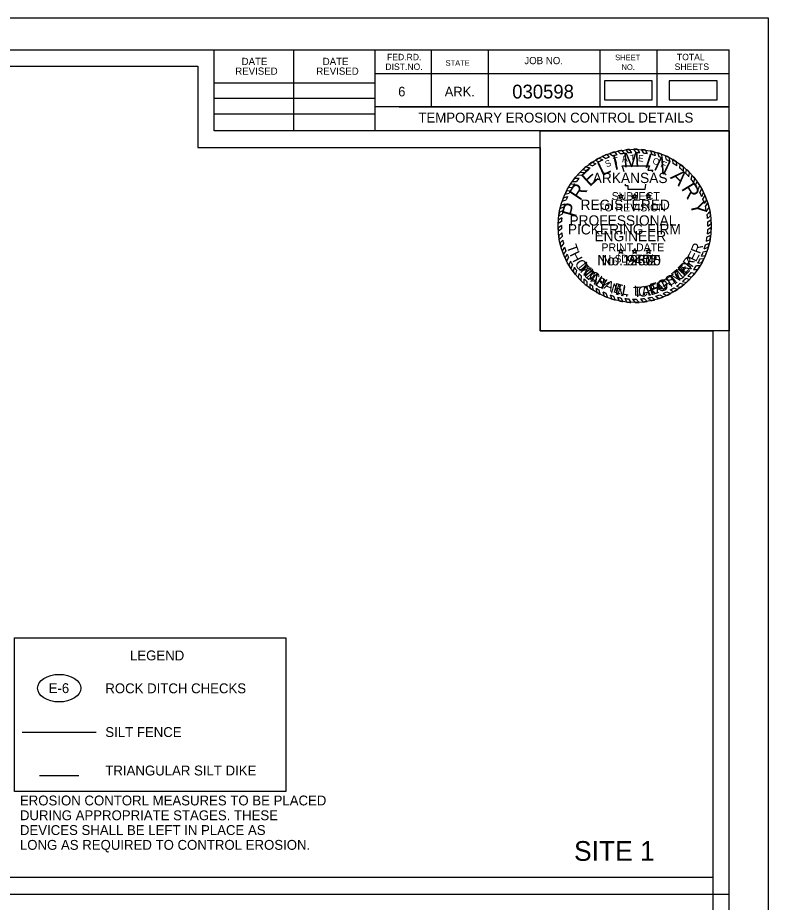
# Model space of a CAD drawing. Extents: x 814841 to 962585, y -174183 to 1802800.
# Drawn here: x 816051 to 816507, y 1802262 to 1802800 of the extents above; entities that cross this region are included whole.
import ezdxf

# ---------------------------------------------------------------- set-up
doc = ezdxf.new("R2010")
doc.units = 0
for name, color, linetype in [('_Silt Dike Legend', 7, 'Continuous'), ('Default', 7, 'Continuous'), ('Legend', 7, 'Continuous'), ('R_Border', 7, 'Continuous'), ('R_Border Notes', 7, 'Continuous'), ('R_Border Plan-Plan', 7, 'Continuous'), ('R_No Plot', 7, 'Continuous'), ('STAMP_PE_CRAFTON', 7, 'Continuous'), ('STAMP_PE_FOSTER', 7, 'Continuous'), ('STAMP_PE_SEAL-INFO', 7, 'Continuous'), ('STAMP_PE_TAEGTMEYER', 7, 'Continuous'), ('STAMP_PE_TXT', 7, 'Continuous'), ('STAMP_PRELIMINARY', 7, 'Continuous'), ('Veg Buffer', 7, 'Continuous')]:
    doc.layers.add(name, color=color, linetype=linetype)

# ---------------------------------------------------------------- blocks, each defined once
blk = doc.blocks.new('E-6')
at = {"layer": 'Default'}
blk.add_ellipse((0, 0), major_axis=(13.15, 0), ratio=0.638788, dxfattribs=at)
blk.add_text('E-6', height=6, dxfattribs=at).set_placement((-6.43, -3))

msp = doc.modelspace()

# ---------------------------------------------------------------- linework, layer by layer
at = {"layer": '_Silt Dike Legend'}
msp.add_line((816063.99, 1802339.12), (816087.99, 1802339.12), dxfattribs=at)
at = {"layer": 'Legend'}
msp.add_line((816053.56, 1802365.5), (816098.58, 1802365.5), dxfattribs=at)
msp.add_lwpolyline([(816048.79, 1802422.91), (816213.79, 1802422.91), (816213.79, 1802329.38), (816048.79, 1802329.38)], close=True, dxfattribs=at)
at = {"layer": 'R_Border'}
for p, q in [((814902.59, 1802780.6), (816483.49, 1802780.6)), ((816170.29, 1802731.2), (816170.29, 1802780.6)), ((816218.69, 1802731.2), (816218.69, 1802780.6)), ((816267.99, 1802780.6), (816267.99, 1802731.2)), ((816302.19, 1802780.6), (816302.19, 1802745.9)), ((816336.89, 1802780.6), (816336.89, 1802745.9)), ((816404.79, 1802780.6), (816404.79, 1802745.9)), ((816439.49, 1802780.6), (816439.49, 1802745.9)), ((816483.49, 1801753.3), (816483.49, 1802780.6)), ((816483.49, 1802765.9), (816267.99, 1802765.9)), ((816483.49, 1802766), (816483.49, 1802766)), ((816170.29, 1802760.5), (816267.99, 1802760.5)), ((816170.29, 1802751.2), (816267.99, 1802751.2)), ((816483.49, 1802745.9), (816267.99, 1802745.9)), ((816282.79, 1802745.9), (816483.49, 1802745.9)), ((816170.29, 1802741.5), (816267.99, 1802741.5)), ((816483.49, 1802731.2), (816170.29, 1802731.2))]:
    msp.add_line(p, q, dxfattribs=at)
at = {"layer": 'R_Border Plan-Plan'}
msp.add_line((814902.59, 1802266.95), (816483.49, 1802266.95), dxfattribs=at)
at = {"layer": 'R_No Plot'}
for points in [[(814840.55, 1802800.08), (816507.25, 1802800.08), (816507.25, 1801733.39), (814840.55, 1801733.39)], [(816473.49, 1802276.95), (814912.59, 1802276.95), (814912.59, 1802770.6), (816160.29, 1802770.6), (816160.29, 1802721.2), (816247.99, 1802721.2), (816368.49, 1802721.2), (816368.49, 1802609.54), (816473.49, 1802609.54)], [(814912.59, 1802770.6), (816160.29, 1802770.6), (816160.29, 1802721.2), (816247.99, 1802721.2), (816368.49, 1802721.2), (816368.49, 1802609.54), (816473.49, 1802609.54), (816473.49, 1801763.3), (814912.59, 1801763.3)], [(816473.49, 1802276.95), (814912.59, 1802276.95), (814912.59, 1802770.6), (816160.29, 1802770.6), (816160.29, 1802721.2), (816247.99, 1802721.2), (816368.49, 1802721.2), (816368.49, 1802609.54), (816473.49, 1802609.54)], [(816368.49, 1802731.2), (816483.49, 1802731.2), (816483.49, 1802609.54), (816368.49, 1802609.54)]]:
    msp.add_lwpolyline(points, close=True, dxfattribs=at)
at = {"layer": 'STAMP_PE_SEAL-INFO'}
for p, q in [((816415.68, 1802718.88), (816417.46, 1802717.16)), ((816418.09, 1802719.36), (816419.59, 1802717.52)), ((816420.67, 1802719.72), (816422.07, 1802717.81)), ((816424.35, 1802717.95), (816422.79, 1802719.92)), ((816426.83, 1802717.98), (816425.44, 1802720.03)), ((816429.12, 1802717.87), (816427.83, 1802719.99)), ((816431.65, 1802717.62), (816430.19, 1802719.84)), ((816433.78, 1802717.3), (816432.5, 1802719.57)), ((816436.59, 1802716.7), (816435.72, 1802719)), ((816438.6, 1802716.16), (816437.81, 1802718.51)), ((816402.11, 1802713.45), (816404.27, 1802712.34)), ((816404.35, 1802714.7), (816406.67, 1802713.58)), ((816406.51, 1802715.76), (816408.45, 1802714.39)), ((816409.05, 1802716.84), (816410.52, 1802715.21)), ((816410.78, 1802717.48), (816412.69, 1802715.95)), ((816413.74, 1802718.39), (816415.18, 1802716.65)), ((816440.86, 1802715.43), (816440.15, 1802717.82)), ((816442.95, 1802714.63), (816442.23, 1802717.11)), ((816445.26, 1802713.6), (816444.75, 1802716.09)), ((816447.49, 1802712.45), (816447.05, 1802715)), ((816449.43, 1802711.32), (816449.23, 1802713.82)), ((816394.47, 1802707.76), (816396.77, 1802707.07)), ((816396.19, 1802709.26), (816398.84, 1802708.76)), ((816398.08, 1802710.9), (816400.35, 1802709.87)), ((816400.18, 1802712.23), (816402.39, 1802711.22)), ((816418.35, 1802709.87), (816435.07, 1802709.87)), ((816418.96, 1802708.34), (816418.35, 1802709.87)), ((816419.48, 1802706.85), (816418.96, 1802708.34)), ((816435.07, 1802709.87), (816433.95, 1802707.41)), ((816451.6, 1802709.89), (816451.44, 1802712.46)), ((816453.4, 1802708.55), (816453.57, 1802710.99)), ((816455.63, 1802706.69), (816455.73, 1802709.31)), ((816457.2, 1802705.23), (816457.54, 1802707.72)), ((816389.45, 1802702.37), (816392.2, 1802702.48)), ((816391.18, 1802704.42), (816393.79, 1802704.23)), ((816392.8, 1802706.14), (816395.52, 1802705.94)), ((816419.51, 1802706.28), (816419.48, 1802706.85)), ((816433.95, 1802707.41), (816437.11, 1802707.41)), ((816437.11, 1802707.41), (816436.39, 1802706.28)), ((816458.99, 1802703.36), (816459.32, 1802705.99)), ((816460.36, 1802701.78), (816461.04, 1802704.14)), ((816385.66, 1802696.79), (816388.11, 1802696.89)), ((816386.89, 1802698.8), (816389.47, 1802698.97)), ((816388.06, 1802700.52), (816390.59, 1802700.49)), ((816420.47, 1802697.73), (816420.34, 1802698.82)), ((816422.04, 1802697.73), (816420.47, 1802697.73)), ((816422.04, 1802695.58), (816422.04, 1802697.73)), ((816432.27, 1802697.27), (816432.19, 1802695.58)), ((816432.66, 1802698.82), (816432.27, 1802697.27)), ((816461.98, 1802699.7), (816462.66, 1802702.19)), ((816463.08, 1802698.12), (816463.97, 1802700.44)), ((816464.62, 1802695.63), (816465.53, 1802698.09)), ((816383.56, 1802692.73), (816386.08, 1802693.25)), ((816384.5, 1802694.68), (816387, 1802695)), ((816432.19, 1802695.58), (816422.04, 1802695.58)), ((816465.62, 1802693.8), (816466.75, 1802696.02)), ((816466.77, 1802691.38), (816467.9, 1802693.81)), ((816467.47, 1802689.7), (816468.79, 1802691.86)), ((816381.11, 1802686.02), (816383.5, 1802686.87)), ((816381.89, 1802688.54), (816384.32, 1802689.22)), ((816382.64, 1802690.57), (816385.17, 1802691.3)), ((816468.45, 1802686.95), (816469.8, 1802689.32)), ((816468.99, 1802685.13), (816470.46, 1802687.39)), ((816382.41, 1802682.75), (816380.08, 1802681.51)), ((816380.59, 1802683.99), (816382.94, 1802684.95)), ((816469.65, 1802682.33), (816471.25, 1802684.57)), ((816470, 1802680.43), (816471.77, 1802682.2)), ((816381.5, 1802676.16), (816379.4, 1802674.87)), ((816381.69, 1802678.28), (816379.5, 1802676.88)), ((816381.98, 1802680.46), (816379.75, 1802679.35)), ((816470.33, 1802677.89), (816472.19, 1802679.57)), ((816470.49, 1802675.8), (816472.44, 1802677.26)), ((816381.42, 1802673.69), (816379.39, 1802672.01)), ((816381.45, 1802671.66), (816379.5, 1802670.03)), ((816470.5, 1802671.18), (816472.59, 1802672.57)), ((816470.55, 1802673.21), (816472.58, 1802674.82)), ((816381.62, 1802669.18), (816379.76, 1802667.4)), ((816381.88, 1802667.03), (816380.11, 1802665.17)), ((816382.27, 1802664.74), (816380.57, 1802662.9)), ((816469.59, 1802664.21), (816471.87, 1802665.19)), ((816470.05, 1802666.71), (816472.26, 1802667.81)), ((816470.3, 1802668.65), (816472.47, 1802669.93)), ((816382.74, 1802662.64), (816381.18, 1802660.57)), ((816383.36, 1802660.41), (816381.89, 1802658.32)), ((816468.32, 1802659.48), (816470.77, 1802660.48)), ((816469.05, 1802661.95), (816471.41, 1802662.96)), ((816384.06, 1802658.29), (816382.66, 1802656.23)), ((816384.89, 1802656.16), (816383.59, 1802654.05)), ((816385.75, 1802654.24), (816384.62, 1802651.94)), ((816466.58, 1802655.01), (816469.02, 1802655.49)), ((816467.65, 1802657.58), (816470.06, 1802658.23)), ((816386.93, 1802651.95), (816385.97, 1802649.5)), ((816388.11, 1802649.93), (816387.19, 1802647.58)), ((816463.55, 1802649.43), (816465.94, 1802649.4)), ((816464.41, 1802650.83), (816466.91, 1802651.1)), ((816465.77, 1802653.33), (816468.21, 1802653.67)), ((816389.12, 1802648.38), (816388.57, 1802645.62)), ((816390.52, 1802646.42), (816390.01, 1802643.77)), ((816392.04, 1802644.54), (816391.61, 1802641.94)), ((816460.31, 1802644.99), (816462.62, 1802644.59)), ((816461.85, 1802646.96), (816464.37, 1802646.97)), ((816393.55, 1802642.85), (816393.25, 1802640.24)), ((816395.17, 1802641.22), (816395.02, 1802638.58)), ((816396.89, 1802639.66), (816396.87, 1802637.01)), ((816398.69, 1802638.19), (816398.78, 1802635.56)), ((816453.74, 1802638.54), (816456.08, 1802637.82)), ((816455.09, 1802639.67), (816457.45, 1802639.02)), ((816457.12, 1802641.53), (816459.33, 1802640.84)), ((816458.4, 1802642.82), (816460.78, 1802642.4)), ((816400.38, 1802636.94), (816400.56, 1802634.35)), ((816402.52, 1802635.53), (816402.82, 1802632.97)), ((816404.27, 1802634.5), (816404.72, 1802631.93)), ((816406.67, 1802633.25), (816407.46, 1802630.64)), ((816408.54, 1802632.41), (816409.4, 1802629.85)), ((816443.31, 1802632.35), (816445.43, 1802631.05)), ((816445.61, 1802633.4), (816448.03, 1802632.34)), ((816447.65, 1802634.47), (816449.73, 1802633.3)), ((816449.72, 1802635.69), (816451.97, 1802634.71)), ((816451.44, 1802636.83), (816453.63, 1802635.88)), ((816411, 1802631.44), (816412.04, 1802628.94)), ((816413.05, 1802630.77), (816414.18, 1802628.32)), ((816415.59, 1802630.08), (816416.65, 1802627.75)), ((816417.57, 1802629.65), (816418.81, 1802627.36)), ((816420.08, 1802629.24), (816421.27, 1802627.04)), ((816422.26, 1802629), (816423.63, 1802626.86)), ((816424.68, 1802628.87), (816426.19, 1802626.8)), ((816426.98, 1802628.86), (816428.7, 1802626.88)), ((816429.57, 1802628.99), (816431.2, 1802627.09)), ((816431.76, 1802629.22), (816433.63, 1802627.43)), ((816433.99, 1802629.57), (816435.93, 1802627.88)), ((816436.45, 1802630.09), (816438.34, 1802628.47)), ((816438.75, 1802630.72), (816440.83, 1802629.23)), ((816441.21, 1802631.53), (816443.43, 1802630.19))]:
    msp.add_line(p, q, dxfattribs=at)
for radius, start, end in [(46.61, 99.7525, 102.7765), (46.61, 93.9381, 96.5517), (46.61, 87.7298, 90.6707), (46.61, 81.9732, 84.8236), (46.61, 75.3125, 77.9426), (46.61, 117.6544, 120.8099), (44.57, 115.6869, 119.1583), (46.61, 111.3124, 114.7026), (44.57, 110.3086, 113.1659), (46.61, 105.2339, 109.0352), (44.57, 104.0352, 107.3615), (44.57, 98.258, 101.0329), (44.57, 92.1102, 95.0367), (44.57, 85.9628, 88.9097), (44.57, 79.9264, 82.696), (44.57, 73.5575, 76.2314), (46.61, 69.6061, 72.3058), (44.57, 67.6248, 70.504), (46.61, 63.1329, 66.2704), (44.57, 61.1558, 64.3784), (46.61, 56.9003, 60.0942), (46.61, 129.7326, 132.5376), (44.57, 127.5297, 130.9683), (46.61, 123.6199, 126.5906), (44.57, 121.9746, 125.11), (44.57, 54.9238, 58.2702), (44.57, 48.3016, 52.0395), (46.61, 50.3492, 53.7159), (46.61, 44.3405, 47.3929), (46.61, 141.6056, 144.4486), (44.57, 139.301, 142.5873), (46.61, 135.4021, 138.3031), (44.57, 133.1331, 136.2562), (44.57, 42.2212, 45.5512), (46.61, 38.1247, 41.2316), (46.61, 147.0072, 149.899), (44.57, 145.0197, 148.2104), (44.57, 36.135, 39.5311), (44.57, 29.9032, 33.6645), (46.61, 31.9614, 35.4294), (46.61, 152.864, 155.5189), (44.57, 151.0315, 153.573), (44.57, 23.7732, 27.2211), (46.61, 25.9391, 29.0125), (46.61, 19.9538, 23.3141), (46.61, 158.4077, 161.0701), (44.57, 162.4331, 165.0013), (44.57, 156.3402, 159.2319), (44.57, 17.6802, 21.4251), (46.61, 13.8421, 17.4447), (46.61, 170.0003, 172.6878), (46.61, 164.3068, 166.894), (44.57, 167.9048, 170.9039), (44.57, 11.5444, 15.2364), (46.61, 7.5852, 10.8621), (46.61, 175.7409, 178.2066), (44.57, 173.73, 176.4734), (44.57, 5.7599, 9.0606), (44.57, 359.7329, 3.0639), (46.61, 1.7215, 4.7268), (46.61, 181.7251, 184.1626), (44.57, 179.6454, 182.2633), (44.57, 353.8632, 357.1274), (46.61, 355.7156, 358.9569), (46.61, 187.4204, 190.1927), (44.57, 185.4539, 188.234), (44.57, 191.2274, 193.9858), (44.57, 348.0778, 351.3435), (46.61, 349.8305, 353.0885), (46.61, 193.0369, 195.9973), (44.57, 196.9675, 199.8353), (44.57, 341.777, 345.0925), (46.61, 343.8925, 347.035), (46.61, 198.8967, 201.6281), (46.61, 204.5479, 207.4328), (44.57, 202.7761, 205.4791), (44.57, 335.6038, 339.1858), (46.61, 337.3837, 340.9933), (46.61, 210.8636, 213.6571), (44.57, 208.7883, 211.7934), (44.57, 323.5851, 327.4407), (46.61, 325.4405, 328.9872), (44.57, 329.5549, 333.2076), (46.61, 331.4037, 334.9332), (46.61, 216.6115, 219.491), (44.57, 214.1838, 217.2747), (44.57, 220.3909, 223.3056), (44.57, 316.6531, 320.3711), (46.61, 318.2846, 321.8043), (46.61, 222.48, 225.3801), (46.61, 228.3665, 231.348), (44.57, 226.2494, 229.2407), (44.57, 232.229, 234.9336), (44.57, 304.823, 308.5143), (46.61, 306.3721, 310.208), (44.57, 310.7744, 314.3161), (46.61, 312.4518, 315.6633), (46.61, 234.295, 236.9452), (44.57, 238.2223, 240.8353), (46.61, 240.1977, 242.8613), (44.57, 244.3204, 246.9486), (44.57, 292.8745, 296.1185), (46.61, 294.6481, 298.2166), (44.57, 299.0768, 302.1724), (46.61, 300.621, 303.8703), (46.61, 246.576, 249.1558), (44.57, 250.3491, 253.1216), (46.61, 252.5967, 255.3252), (44.57, 256.505, 259.1192), (46.61, 258.4433, 261.1398), (44.57, 262.3783, 265.2012), (46.61, 264.1978, 267.1009), (44.57, 268.3215, 271.277), (44.57, 274.6157, 277.4486), (46.61, 276.4239, 279.4357), (44.57, 280.3459, 283.5814), (46.61, 282.3199, 285.3702), (44.57, 286.6423, 289.9783), (46.61, 288.5709, 291.9733), (46.61, 270.2548, 273.3361)]:
    msp.add_arc((816425.99, 1802673.42), radius, start, end, dxfattribs=at)
at = {"layer": 'STAMP_PE_TXT'}
for p, q in [((816416.88, 1802691.27), (816415.89, 1802691.99)), ((816415.89, 1802691.99), (816417.12, 1802691.99)), ((816417.12, 1802691.99), (816417.5, 1802693.16)), ((816417.5, 1802693.16), (816417.88, 1802691.99)), ((816417.88, 1802691.99), (816419.1, 1802691.99)), ((816419.1, 1802691.99), (816418.11, 1802691.27)), ((816425.37, 1802691.27), (816424.38, 1802691.99)), ((816424.38, 1802691.99), (816425.61, 1802691.99)), ((816425.61, 1802691.99), (816425.99, 1802693.16)), ((816425.99, 1802693.16), (816426.37, 1802691.99)), ((816426.37, 1802691.99), (816427.59, 1802691.99)), ((816427.59, 1802691.99), (816426.6, 1802691.27)), ((816433.86, 1802691.27), (816432.87, 1802691.99)), ((816432.87, 1802691.99), (816434.1, 1802691.99)), ((816434.1, 1802691.99), (816434.48, 1802693.16)), ((816434.48, 1802693.16), (816434.86, 1802691.99)), ((816434.86, 1802691.99), (816436.08, 1802691.99)), ((816436.08, 1802691.99), (816435.09, 1802691.27)), ((816416.51, 1802690.11), (816416.88, 1802691.27)), ((816417.5, 1802690.83), (816416.51, 1802690.11)), ((816418.49, 1802690.11), (816417.5, 1802690.83)), ((816418.11, 1802691.27), (816418.49, 1802690.11)), ((816425, 1802690.11), (816425.37, 1802691.27)), ((816425.99, 1802690.83), (816425, 1802690.11)), ((816426.98, 1802690.11), (816425.99, 1802690.83)), ((816426.6, 1802691.27), (816426.98, 1802690.11)), ((816433.48, 1802690.11), (816433.86, 1802691.27)), ((816434.48, 1802690.83), (816433.48, 1802690.11)), ((816435.47, 1802690.11), (816434.48, 1802690.83)), ((816435.09, 1802691.27), (816435.47, 1802690.11)), ((816417.12, 1802658.46), (816417.5, 1802659.62)), ((816417.5, 1802659.62), (816417.88, 1802658.46)), ((816425.61, 1802658.46), (816425.99, 1802659.62)), ((816425.99, 1802659.62), (816426.37, 1802658.46)), ((816434.1, 1802658.46), (816434.48, 1802659.62)), ((816434.48, 1802659.62), (816434.86, 1802658.46)), ((816416.88, 1802657.74), (816415.89, 1802658.46)), ((816415.89, 1802658.46), (816417.12, 1802658.46)), ((816416.51, 1802656.57), (816416.88, 1802657.74)), ((816417.5, 1802657.29), (816416.51, 1802656.57)), ((816418.49, 1802656.57), (816417.5, 1802657.29)), ((816417.88, 1802658.46), (816419.1, 1802658.46)), ((816419.1, 1802658.46), (816418.11, 1802657.74)), ((816418.11, 1802657.74), (816418.49, 1802656.57)), ((816425.37, 1802657.74), (816424.38, 1802658.46)), ((816424.38, 1802658.46), (816425.61, 1802658.46)), ((816425, 1802656.57), (816425.37, 1802657.74)), ((816425.99, 1802657.29), (816425, 1802656.57)), ((816426.98, 1802656.57), (816425.99, 1802657.29)), ((816426.37, 1802658.46), (816427.59, 1802658.46)), ((816427.59, 1802658.46), (816426.6, 1802657.74)), ((816426.6, 1802657.74), (816426.98, 1802656.57)), ((816433.86, 1802657.74), (816432.87, 1802658.46)), ((816432.87, 1802658.46), (816434.1, 1802658.46)), ((816433.48, 1802656.57), (816433.86, 1802657.74)), ((816434.48, 1802657.29), (816433.48, 1802656.57)), ((816435.47, 1802656.57), (816434.48, 1802657.29)), ((816434.86, 1802658.46), (816436.08, 1802658.46)), ((816436.08, 1802658.46), (816435.09, 1802657.74)), ((816435.09, 1802657.74), (816435.47, 1802656.57))]:
    msp.add_line(p, q, dxfattribs=at)
at = {"layer": 'STAMP_PRELIMINARY'}
msp.add_circle((816425.99, 1802673.42), 46.61, dxfattribs=at)
at = {"layer": 'Veg Buffer'}
for points in [[(816407.55, 1802750.13), (816436.72, 1802750.13), (816436.72, 1802761.68), (816407.55, 1802761.68)], [(816446.9, 1802750.13), (816476.07, 1802750.13), (816476.07, 1802761.68), (816446.9, 1802761.68)]]:
    msp.add_lwpolyline(points, close=True, dxfattribs=at)

# ---------------------------------------------------------------- block references
at = {"layer": 'Legend', "rotation": -1.8065126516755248e-10}
msp.add_blockref('E-6', (816076.07, 1802392.22), dxfattribs=at)

# ---------------------------------------------------------------- texts
at = {"layer": 'Legend'}
for s, p in [('LEGEND', (816119.1, 1802409.12)), ('ROCK DITCH CHECKS', (816104.1, 1802389.12)), ('SILT FENCE', (816104.1, 1802362.5)), ('TRIANGULAR SILT DIKE', (816104.1, 1802339.12)), ('EROSION CONTORL MEASURES TO BE PLACED', (816052.16, 1802320.89)), ('DURING APPROPRIATE STAGES. THESE ', (816052.16, 1802311.89)), ('DEVICES SHALL BE LEFT IN PLACE AS ', (816052.16, 1802302.89)), ('LONG AS REQUIRED TO CONTROL EROSION.', (816052.16, 1802293.89))]:
    msp.add_text(s, height=6, dxfattribs=at).set_placement(p)
at = {"layer": 'R_Border'}
for s, height, p in [('FED.RD.', 3.91, (816275.39, 1802774.2)), ('SHEET', 3.42, (816414.09, 1802774.2)), ('TOTAL', 3.91, (816451.69, 1802774.2)), ('DATE', 4.396, (816186.98, 1802771.28)), ('DATE', 4.396, (816236.28, 1802771.28)), ('DIST.NO.', 3.91, (816274.39, 1802768.3)), ('STATE', 3.42, (816310.99, 1802770.8)), ('JOB NO.', 4.396, (816358.89, 1802771.8)), ('SHEETS', 3.91, (816450.29, 1802768.3)), ('REVISED', 4.396, (816183.08, 1802765.38)), ('REVISED', 4.396, (816232.38, 1802765.38)), ('NO.', 3.42, (816417.99, 1802768.3)), ('6', 5.86, (816282.19, 1802752.2)), ('ARK.', 5.861, (816310.49, 1802752.2)), ('SITE 1', 12, (816389.12, 1802287.19))]:
    msp.add_text(s, height=height, dxfattribs=at).set_placement(p)
at = {"layer": 'R_Border Notes'}
for s, height, p in [('030598', 8.4, (816351.54, 1802750.93)), ('TEMPORARY EROSION CONTROL DETAILS', 6, (816294.49, 1802736.3))]:
    msp.add_text(s, height=height, dxfattribs=at).set_placement(p)
at = {"layer": 'STAMP_PE_CRAFTON'}
msp.add_text('No. 12370', height=6.25, dxfattribs=at).set_placement((816403.3, 1802649.4))
for s, rotation, p in [('T', 310.7442, (816390.82, 1802647.9)), ('N', 49.2411, (816457.4, 1802643.53)), ('O', 317.6422, (816394.15, 1802643.85)), ('N', 324.4537, (816398.38, 1802639.92)), ('T', 34.1136, (816448.87, 1802636.61)), ('O', 41.8391, (816453.16, 1802639.62)), ('Y', 331.1686, (816403.55, 1802636.34)), ('N', 347.4752, (816413.82, 1802631.76)), ('R', 14.8189, (816433.83, 1802630.7)), ('A', 20.5125, (816439.39, 1802632.19)), ('F', 28.7821, (816444.29, 1802634.06)), ('C', 6.0117, (816428.34, 1802630.12)), ('.', 356.8926, (816419.97, 1802630.38))]:
    msp.add_text(s, height=6.25, rotation=rotation, dxfattribs=at).set_placement(p)
at = {"layer": 'STAMP_PE_FOSTER'}
msp.add_text('No. 9402', height=6.25, dxfattribs=at).set_placement((816405.92, 1802649.4))
for s, rotation, p in [('R', 54.5031, (816459.61, 1802647.47)), ('M', 308.339, (816391.57, 1802648.53)), ('E', 46.9613, (816455.99, 1802643.37)), ('I', 314.1842, (816395.55, 1802643.84)), ('C', 319.8733, (816397.33, 1802642.07)), ('H', 327.7235, (816401.97, 1802638.39)), ('S', 31.7234, (816446.94, 1802636.48)), ('T', 39.4194, (816451.7, 1802639.62)), ('A', 335.7276, (816406.88, 1802635.48)), ('E', 343.5779, (816412.56, 1802633.13)), ('F', 15.8691, (816436.16, 1802632.19)), ('O', 23.719, (816441.38, 1802633.83)), ('L', 350.8115, (816417.86, 1802631.74)), ('L', 1.2666, (816425.55, 1802630.96)), ('.', 6.8035, (816430.79, 1802631.25))]:
    msp.add_text(s, height=6, rotation=rotation, dxfattribs=at).set_placement(p)
at = {"layer": 'STAMP_PE_TAEGTMEYER'}
for s, rotation, p in [('T', 289.646, (816384.46, 1802660.97)), ('R', 69.57, (816465.71, 1802655.99)), ('H', 296.7339, (816386.26, 1802656.04)), ('Y', 53.9986, (816459.87, 1802646.38)), ('E', 63.0984, (816463.22, 1802651.08)), ('O', 303.7708, (816389.22, 1802650.5)), ('M', 314.2033, (816392.5, 1802645.75)), ('E', 46.8094, (816456.18, 1802642.3)), ('A', 321.0594, (816397.3, 1802640.93)), ('T', 31.466, (816446.49, 1802635.19)), ('M', 39.3, (816450.98, 1802637.91)), ('S', 327.8239, (816401.44, 1802637.71)), ('N', 344.2727, (816410.92, 1802632.67)), ('E', 17.6836, (816435.74, 1802631.07)), ('G', 23.3052, (816440.99, 1802632.73)), ('T', 3.0061, (816425.31, 1802630.02)), ('A', 8.9826, (816430.54, 1802630.3)), ('.', 350.6464, (816416.98, 1802631.01))]:
    msp.add_text(s, height=6.25, rotation=rotation, dxfattribs=at).set_placement(p)
msp.add_text('No. 19605', height=6.25, dxfattribs=at).set_placement((816403.3, 1802649.4))
at = {"layer": 'STAMP_PE_TXT'}
for s, rotation, p in [('S', 23.5541, (816408.98, 1802708.93)), ('T', 16.311, (816413.59, 1802710.8)), ('A', 9.0679, (816418.41, 1802712.06)), ('T', 1.8248, (816423.34, 1802712.71)), ('E', 355.2002, (816427.89, 1802712.75)), ('O', 342.2506, (816436.52, 1802711.37)), ('F', 335.0075, (816441.35, 1802709.68))]:
    msp.add_text(s, height=3.91, rotation=rotation, dxfattribs=at).set_placement(p)
for s, p in [('ARKANSAS', (816400.45, 1802699.47)), ('REGISTERED', (816393.07, 1802683.12)), ('PROFESSIONAL', (816386.33, 1802673.61)), ('ENGINEER', (816401.53, 1802664.11))]:
    msp.add_text(s, height=6.25, dxfattribs=at).set_placement(p)
at = {"layer": 'STAMP_PRELIMINARY'}
for s, rotation, p in [('I', 12.5248, (816413.67, 1802707.35)), ('M', 3.1074, (816419.17, 1802708.89)), ('I', 342.3164, (816431.5, 1802709.23)), ('N', 333.9382, (816437.04, 1802707.86)), ('E', 42.3578, (816398.62, 1802696.9)), ('L', 25.513, (816406.03, 1802703.55)), ('A', 315.6579, (816447.21, 1802702.73)), ('R', 56.2292, (816392.84, 1802688.23)), ('R', 301.3831, (816454.05, 1802696.16)), ('P', 73.913, (816390.09, 1802678.12)), ('Y', 283.2593, (816459.5, 1802687.23))]:
    msp.add_text(s, height=9, rotation=rotation, dxfattribs=at).set_placement(p)
for s, height, p in [('SUBJECT', 4.8, (816411.99, 1802689.16)), ('TO REVISION', 4.8, (816403.66, 1802682.24)), ('PICKERING FIRM', 6.25, (816385.35, 1802668.23)), ('PRINT DATE', 4.8, (816405.77, 1802657.99)), ('$DATE$', 4.8, (816414.16, 1802651.07))]:
    msp.add_text(s, height=height, dxfattribs=at).set_placement(p)

doc.saveas('drawing.dxf')
